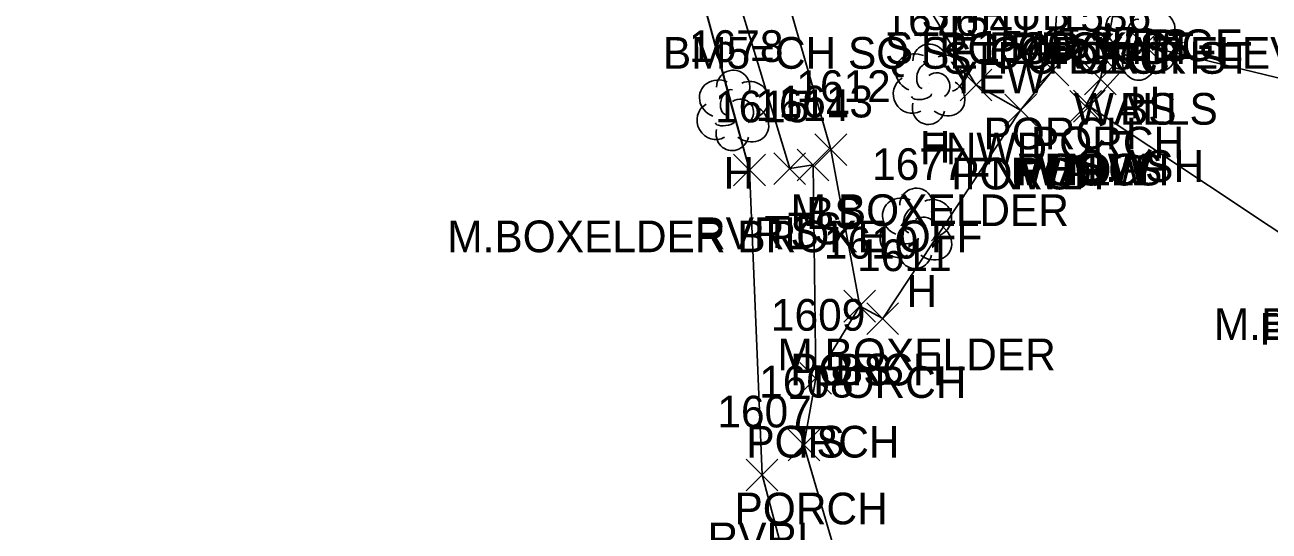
# Model space of a CAD drawing. Extents: x 1461855 to 1464118, y 556196 to 557441.
# Drawn here: x 1462290.7 to 1462369.1, y 556362.8 to 556394.7 of the extents above; entities that cross this region are included whole.
import ezdxf

# ---------------------------------------------------------------- set-up
doc = ezdxf.new("R2010")
doc.units = 0
for name, color, linetype in [('C_C', 7, 'Continuous'), ('L_A', 7, 'Continuous'), ('L_C', 7, 'Continuous'), ('L_I', 7, 'Continuous'), ('L_TIC', 7, 'Continuous'), ('LAWE', 7, 'Continuous'), ('LBC', 7, 'Continuous'), ('LBF', 7, 'Continuous'), ('LELB', 7, 'Continuous'), ('LFNC', 7, 'Continuous'), ('LSOGP', 7, 'Continuous'), ('LTD', 7, 'Continuous'), ('LWS', 7, 'Continuous')]:
    doc.layers.add(name, color=color, linetype=linetype)

msp = doc.modelspace()

# ---------------------------------------------------------------- linework, layer by layer
at = {"layer": 'L_TIC'}
for points in [[(1462360.289, 556392.392), (1462362.289, 556394.392)], [(1462362.289, 556392.392), (1462360.289, 556394.392)], [(1462360.289, 556392.392), (1462362.289, 556394.392)], [(1462362.289, 556392.392), (1462360.289, 556394.392)], [(1462354.505, 556390.838), (1462356.505, 556392.838)], [(1462356.505, 556390.838), (1462354.505, 556392.838)], [(1462349.653, 556389.897), (1462351.653, 556391.897)], [(1462351.653, 556389.897), (1462349.653, 556391.897)], [(1462357.498, 556390.267), (1462359.498, 556392.267)], [(1462359.498, 556390.267), (1462357.498, 556392.267)], [(1462352.47, 556388.311), (1462354.47, 556390.311)], [(1462354.47, 556388.311), (1462352.47, 556390.311)], [(1462352.47, 556388.311), (1462354.47, 556390.311)], [(1462354.47, 556388.311), (1462352.47, 556390.311)], [(1462356.566, 556388.56), (1462358.566, 556390.56)], [(1462358.566, 556388.56), (1462356.566, 556390.56)], [(1462356.566, 556388.56), (1462358.566, 556390.56)], [(1462358.566, 556388.56), (1462356.566, 556390.56)], [(1462356.799, 556388.562), (1462358.799, 556390.562)], [(1462358.799, 556388.562), (1462356.799, 556390.562)], [(1462356.799, 556388.562), (1462358.799, 556390.562)], [(1462358.799, 556388.562), (1462356.799, 556390.562)], [(1462340.511, 556385.823), (1462342.511, 556387.823)], [(1462342.511, 556385.823), (1462340.511, 556387.823)], [(1462339.394, 556384.851), (1462341.394, 556386.851)], [(1462341.394, 556384.851), (1462339.394, 556386.851)], [(1462335.388, 556384.542), (1462337.388, 556386.542)], [(1462337.388, 556384.542), (1462335.388, 556386.542)], [(1462337.925, 556384.624), (1462339.925, 556386.624)], [(1462339.925, 556384.624), (1462337.925, 556386.624)], [(1462342.338, 556375.947), (1462344.338, 556377.947)], [(1462344.338, 556375.947), (1462342.338, 556377.947)], [(1462342.338, 556375.947), (1462344.338, 556377.947)], [(1462344.338, 556375.947), (1462342.338, 556377.947)], [(1462343.78, 556375.159), (1462345.78, 556377.159)], [(1462345.78, 556375.159), (1462343.78, 556377.159)], [(1462339.565, 556371.399), (1462341.565, 556373.399)], [(1462341.565, 556371.399), (1462339.565, 556373.399)], [(1462339.565, 556371.399), (1462341.565, 556373.399)], [(1462341.565, 556371.399), (1462339.565, 556373.399)], [(1462338.82, 556367.184), (1462340.82, 556369.184)], [(1462340.82, 556367.184), (1462338.82, 556369.184)], [(1462336.181, 556365.3), (1462338.181, 556367.3)], [(1462338.181, 556365.3), (1462336.181, 556367.3)]]:
    msp.add_lwpolyline(points, dxfattribs=at)
at = {"layer": 'LAWE'}
msp.add_lwpolyline([(1462349.416, 556312.261), (1462347.875, 556323.015), (1462343.781, 556341.464), (1462337.181, 556366.3), (1462336.388, 556385.542), (1462332.388, 556400.161), (1462328.247, 556406.014), (1462322.28, 556416.088), (1462319.217, 556425.247), (1462318.05, 556436.547), (1462318.359, 556451.215), (1462318.431, 556468.892), (1462315.755, 556484.128), (1462311.368, 556498.702), (1462302.601, 556511.598)], dxfattribs=at)
at = {"layer": 'LBC'}
msp.add_lwpolyline([(1462372.901, 556379.511), (1462357.799, 556389.562), (1462357.566, 556389.56)], dxfattribs=at)
at = {"layer": 'LBF'}
for points in [[(1462355.858, 556397.219), (1462355.505, 556391.838), (1462353.47, 556389.311)], [(1462359.532, 556396.605), (1462358.498, 556391.267), (1462357.566, 556389.56)], [(1462344.78, 556376.159), (1462353.47, 556389.311)], [(1462349.924, 556345.536), (1462348.47, 556343.541), (1462348.387, 556343.345), (1462347.428, 556342.103), (1462339.82, 556368.184), (1462340.565, 556372.399), (1462343.338, 556376.947), (1462344.78, 556376.159)]]:
    msp.add_lwpolyline(points, dxfattribs=at)
at = {"layer": 'LELB'}
for points in [[(1462340.565, 556372.399), (1462340.394, 556385.851), (1462338.925, 556385.624), (1462334.245, 556401.082), (1462329.929, 556412.702)], [(1462343.338, 556376.947), (1462341.511, 556386.823), (1462337.254, 556401.642)], [(1462420.05, 556348.803), (1462413.651, 556364.514), (1462410.639, 556367.909), (1462395.045, 556380.654), (1462391.534, 556382.101), (1462377.144, 556389.534), (1462361.289, 556393.392)]]:
    msp.add_lwpolyline(points, dxfattribs=at)
at = {"layer": 'LFNC'}
msp.add_lwpolyline([(1462353.47, 556389.311), (1462350.653, 556390.897), (1462344.337, 556401.257)], dxfattribs=at)
at = {"layer": 'LSOGP'}
msp.add_lwpolyline([(1462152.286, 556411.553), (1462201.558, 556420.694), (1462202.678, 556419.763), (1462203.798, 556418.832), (1462262.402, 556416.239), (1462263.085, 556416.638), (1462263.768, 556417.037), (1462264.45, 556417.436), (1462265.133, 556417.835), (1462322.28, 556416.088), (1462328.247, 556406.014), (1462332.388, 556400.161), (1462335.319, 556389.349), (1462336.388, 556385.542), (1462337.181, 556366.3), (1462343.781, 556341.464)], dxfattribs=at)
at = {"layer": 'LTD'}
for p, q in [((1462360.928, 556393.788), (1462360.928, 556393.788)), ((1462360.928, 556393.788), (1462360.928, 556393.788)), ((1462347.684, 556391), (1462347.684, 556391)), ((1462347.684, 556391), (1462347.684, 556391)), ((1462335.319, 556389.349), (1462335.319, 556389.349)), ((1462335.319, 556389.349), (1462335.319, 556389.349)), ((1462346.852, 556381.905), (1462346.852, 556381.905)), ((1462346.852, 556381.905), (1462346.852, 556381.905))]:
    msp.add_line(p, q, dxfattribs=at)
for centre in [(1462347.731, 556392.434), (1462335.365, 556390.783), (1462346.899, 556383.339)]:
    msp.add_arc(centre, 1.047, 335.52715, 180.95627, dxfattribs=at)
for centre, major_axis, ratio, start_param, end_param in [((1462360.137, 556394.454), (1.21, -0.512), 0.895232, 1.570796, 4.712389), ((1462361.97, 556394.371), (-1.141, -0.483), 0.949671, 1.570796, 4.712389), ((1462360.72, 556394.246), (-0.208, -0.792), 0.645439, 3.141593, 6.283185), ((1462359.845, 556393.079), (0.584, -1.042), 0.959034, 3.141593, 6.283185), ((1462361.428, 556393.621), (-0.5, 0.667), 0.989748, 3.141593, 6.283185), ((1462360.47, 556393.038), (-0.625, -0.083), 0.423636, 0, 3.141593), ((1462361.928, 556392.954), (-1.09, 0.792), 0.841452, 1.570796, 4.712389), ((1462346.892, 556391.667), (1.21, -0.512), 0.895232, 1.570796, 4.712389), ((1462347.475, 556391.458), (-0.208, -0.792), 0.645439, 3.141593, 6.283185), ((1462348.725, 556391.584), (-1.141, -0.483), 0.949671, 1.570796, 4.712389), ((1462360.929, 556392.288), (0.265, 1.061), 0.942809, 1.570796, 4.712389), ((1462348.184, 556390.834), (-0.5, 0.667), 0.989748, 3.141593, 6.283185), ((1462334.527, 556390.016), (1.21, -0.512), 0.895232, 1.570796, 4.712389), ((1462336.36, 556389.933), (-1.141, -0.483), 0.949671, 1.570796, 4.712389), ((1462346.601, 556390.292), (0.584, -1.042), 0.959034, 3.141593, 6.283185), ((1462348.684, 556390.167), (-1.09, 0.792), 0.841452, 1.570796, 4.712389), ((1462335.11, 556389.808), (-0.208, -0.792), 0.645439, 3.141593, 6.283185), ((1462335.819, 556389.183), (-0.5, 0.667), 0.989748, 3.141593, 6.283185), ((1462347.226, 556390.25), (-0.625, -0.083), 0.423636, 0, 3.141593), ((1462334.235, 556388.641), (0.584, -1.042), 0.959034, 3.141593, 6.283185), ((1462336.319, 556388.516), (-1.09, 0.792), 0.841452, 1.570796, 4.712389), ((1462347.684, 556389.5), (0.265, 1.061), 0.942809, 1.570796, 4.712389), ((1462334.86, 556388.599), (-0.625, -0.083), 0.423636, 0, 3.141593), ((1462335.319, 556387.849), (0.265, 1.061), 0.942809, 1.570796, 4.712389), ((1462346.06, 556382.572), (1.21, -0.512), 0.895232, 1.570796, 4.712389), ((1462347.893, 556382.489), (-1.141, -0.483), 0.949671, 1.570796, 4.712389), ((1462346.643, 556382.363), (-0.208, -0.792), 0.645439, 3.141593, 6.283185), ((1462345.769, 556381.197), (0.584, -1.042), 0.959034, 3.141593, 6.283185), ((1462347.352, 556381.739), (-0.5, 0.667), 0.989748, 3.141593, 6.283185), ((1462347.852, 556381.072), (-1.09, 0.792), 0.841452, 1.570796, 4.712389), ((1462346.852, 556380.405), (0.265, 1.061), 0.942809, 1.570796, 4.712389), ((1462346.394, 556381.155), (-0.625, -0.083), 0.423636, 0, 3.141593)]:
    msp.add_ellipse(centre, major_axis=major_axis, ratio=ratio, start_param=start_param, end_param=end_param, dxfattribs=at)
at = {"layer": 'LWS'}
msp.add_lwpolyline([(1462357.799, 556389.562), (1462361.289, 556393.392)], dxfattribs=at)

# ---------------------------------------------------------------- texts
at = {"layer": 'C_C'}
msp.add_text('BM5=CH SQ SE COR XAT ELEV=', height=2, dxfattribs=at).set_placement((1462330.929, 556391.921))
at = {"layer": 'L_A'}
for s, p in [('SHRUB', (1462347.223, 556394.372)), ('STPC DECK ST', (1462344.921, 556392.219)), ('PORCH', (1462351.48, 556392.219)), ('HEDGE', (1462357.979, 556392.402)), ('TS', (1462360.688, 556392.402)), ('STPC DECK ST', (1462348.595, 556391.605)), ('PORCH', (1462355.154, 556391.605)), ('H', (1462360.361, 556388.788)), ('WALLS', (1462356.832, 556388.392)), ('BS', (1462359.73, 556388.392)), ('PORCH', (1462351.127, 556386.838)), ('H', (1462347.117, 556386)), ('FNWD', (1462347.118, 556385.897)), ('PORCH', (1462354.12, 556386.267)), ('H', (1462334.752, 556384.349)), ('PORCH', (1462349.092, 556384.311)), ('FNWD', (1462349.935, 556384.311)), ('WALLS', (1462353.342, 556384.562)), ('PORCH', (1462353.188, 556384.56)), ('HOW', (1462354.952, 556384.56)), ('HOW', (1462355.185, 556384.562)), ('BS', (1462339.952, 556381.823)), ('RVRL', (1462332.954, 556380.542)), ('TS', (1462337.334, 556380.624)), ('TS', (1462338.804, 556380.851)), ('H', (1462346.285, 556376.905)), ('PORCH', (1462368.523, 556374.511)), ('PORCH', (1462338.96, 556371.947)), ('BS', (1462341.779, 556371.947)), ('PORCH', (1462340.402, 556371.159)), ('PORCH', (1462336.187, 556367.399)), ('TS', (1462338.974, 556367.399)), ('PORCH', (1462335.442, 556363.184)), ('RVRL', (1462333.747, 556361.3))]:
    msp.add_text(s, height=2, dxfattribs=at).set_placement(p)
at = {"layer": 'L_C'}
for s, p in [('YEW', (1462348.994, 556390.372)), ('S.ASH', (1462357.007, 556384.788)), ('M.BOXELDER', (1462338.983, 556382)), ('M.BOXELDER BROKE OFF', (1462317.342, 556380.349)), ('M.BOXELDER', (1462365.651, 556374.817)), ('M.BOXELDER', (1462338.151, 556372.905))]:
    msp.add_text(s, height=2, dxfattribs=at).set_placement(p)
at = {"layer": 'L_I'}
for s, p in [('1536', (1462355.75, 556394.267)), ('1676', (1462344.889, 556394)), ('1541', (1462348.527, 556393.897)), ('1678', (1462332.578, 556392.349)), ('1540', (1462350.691, 556392.311)), ('1540', (1462350.691, 556392.311)), ('1537', (1462354.873, 556392.56)), ('1537', (1462354.873, 556392.56)), ('1532', (1462355.106, 556392.562)), ('1532', (1462355.106, 556392.562)), ('1612', (1462339.338, 556389.823)), ('1613', (1462338.221, 556388.851)), ('1615', (1462334.214, 556388.542)), ('1614', (1462336.752, 556388.624)), ('1677', (1462344.112, 556384.905)), ('1610', (1462341.078, 556379.947)), ('1610', (1462341.078, 556379.947)), ('1611', (1462343.174, 556379.159)), ('1609', (1462337.738, 556375.399)), ('1609', (1462337.738, 556375.399)), ('1608', (1462337.001, 556371.184)), ('1607', (1462334.362, 556369.3))]:
    msp.add_text(s, height=2, dxfattribs=at).set_placement(p)

doc.saveas('drawing.dxf')
